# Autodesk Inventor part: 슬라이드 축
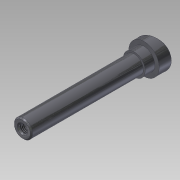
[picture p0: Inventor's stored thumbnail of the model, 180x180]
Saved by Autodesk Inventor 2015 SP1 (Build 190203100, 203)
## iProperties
Company: 한국ATC센터
Created: 2014-07
Part Number: 슬라이드 축
Document SubType Name: 모델링
Designer: KYOUNG IL JANG
Mass: 169.348 g
Surface Area: 67.586 cm^2
Volume: 21.5729 cm^3
Density: 7.85 g/cm^3
Material: 강철, 연강
Appearance: 반연마
변환 표준: STEP AP214IS
파일 이름: C:\Users\SeoGD\Desktop\?쒗뿕\異?stp
전처리기: Build: 253, Release: 2010 SP1 - Date: Wed 07/29/2009
전송 단위: 밀리미터
불확실성: 0.01
Author: KYOUNG IL JANG
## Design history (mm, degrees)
sketch "스케치1"
  geometry: L1 (0, 100)-(7.5, 100); L2 (7.5, 100)-(7.5, 0); L3 (7.5, 0)-(12.5, 0); L4 (12.5, 0)-(12.5, -17); L5 (12.5, -17)-(0, -17); L6 (0, -17)-(0, 100); 1 further point
  constraints: 12 end point, 2 parallel, 2 point on line, 1 perpendicular, 1 vertical
  dimensions: "d0" = 100 distance from line of L1 point (0, 0); "d1" = 15 diameter of L2 L6; "d2" = 25 diameter of L4 L6; "d3" = 17 distance of L3.end L4.end
revolve "회전1" sketch "스케치1" stored, may be unused: angle "d4" = 90 deg
sketch "스케치2"
  geometry: L1 (12.5, 0)-(12.5, -17) reference; L2 (-12.5, -17)-(12.5, -17) reference; L3 (-12.5, 0)-(-12.5, -17) reference; L4 (12.5, -5)-(-12.5, -11.699); L5 (-12.5, 0)-(12.5, 0) reference; 1 further point
  constraints: 2 end point, 2 point on line
  dimensions: "d5" = 75 deg angle of L1 L4; "d6" = 5 distance from line of L4.start L5
extrude "돌출1" cut sketch "스케치2" stored distance "d7" = 10; taper "d8" = 0 deg
chamfer "모따기1" distance "d9" = 1; stored, may be unused: second distance "d10" = 2, angle "d11" = 45 deg
fillet "모깎기1" dims "d12" = 0.5
hole "구멍1" diameter "d15" = 6.647; stored, may be unused: countersink angle "d19" = 90 deg, drill point angle "d21" = 118 deg; dims "d13" = 10, "d14" = 10, "d16" = 17, "d17" = 4, "d18" = 2, "d20" = 20
chamfer "모따기2" distance "d22" = 1; stored, may be unused: second distance "d23" = 2, angle "d24" = 45 deg
sketch "스케치3"
  geometry: C1 r 9 at (0, 0); 1 further point
  constraints: 1 centre point, 1 coincident
  dimensions: "d25" = 18 diameter of C1
extrude "돌출2" join sketch "스케치3" distance "d26" = 8; taper "d27" = 0 deg
node "솔리드1"
node "솔리드 본체"
node "곡면 본체"
node "솔리드2"
